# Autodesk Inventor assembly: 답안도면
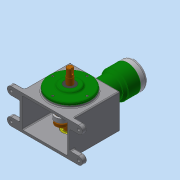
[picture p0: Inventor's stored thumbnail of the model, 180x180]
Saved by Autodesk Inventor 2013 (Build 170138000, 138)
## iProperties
Created: 2016-11
Part Number: 답안도면
Document SubType Name: Assembly
Designer: dgall
Author: dgall
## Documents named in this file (16)
- C:\Users\dgall\Desktop\361107V1012\답안조립품.iam
- C:\Users\dgall\Desktop\361107V1012\본체.ipt
- C:\Users\dgall\Desktop\361107V1012\베어링 20 x 47 x 14.ipt
- C:\Users\dgall\Desktop\361107V1012\메인크랭크축.ipt
- C:\Users\dgall\Desktop\361107V1012\베어링 NA 4902.ipt
- C:\Users\dgall\Desktop\361107V1012\크랭크보조축.ipt
- C:\Users\dgall\Desktop\361107V1012\앞커버.ipt
- C:\Users\dgall\Desktop\361107V1012\오일 실 20 35 8.ipt
- C:\Users\dgall\Desktop\361107V1012\실린더.ipt
- C:\Users\dgall\Desktop\361107V1012\피스톤.ipt
- C:\Users\dgall\Desktop\361107V1012\커넥팅로드.ipt
- C:\Users\dgall\Desktop\361107V1012\피스톤핀.ipt
- C:\Users\dgall\Desktop\361107V1012\실린더헤드.ipt
- C:\Users\dgall\Desktop\361107V1012\가변스프링.ipt
- C:\Users\dgall\Desktop\361107V1012\볼트 M4 x 8.ipt
- C:\Users\dgall\Desktop\361107V1012\볼트 M5 x 20.ipt
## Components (15 placed, 5 different names)
1. 피스톤:1
2. 피스톤핀:1
3. 가변스프링:1
4. ISO 4762 M5 x 20:1
5. ISO 4762 M5 x 20:2
6. ISO 4762 M5 x 20:3
7. ISO 4762 M5 x 20:4
8. ISO 4762 M4 x 8:1
9. ISO 4762 M4 x 8:2
10. ISO 4762 M4 x 8:3
11. ISO 4762 M4 x 8:4
12. ISO 4762 M4 x 8:5
13. ISO 4762 M4 x 8:6
14. ISO 4762 M4 x 8:7
15. ISO 4762 M4 x 8:8
